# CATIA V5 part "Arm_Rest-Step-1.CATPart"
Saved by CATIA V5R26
Part number: Arm_Rest
Bounding box of the stored display mesh (mm): x 766.704 to 1406.055, y -782.252 to -669.745, z 394.638 to 524.862
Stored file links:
  D:\LinkedIn Learning\NURBS\CATIA\Class Parts\Arm_Rest-Step-1.CATPart
  D:\LinkedIn Learning\NURBS\Arm_Rest.CATPart
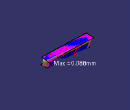
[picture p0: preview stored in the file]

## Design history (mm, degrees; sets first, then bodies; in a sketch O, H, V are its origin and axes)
AxisSystem1: origin (0, 0, 0), X (1, 0, 0), Y (0, 1, 0), Z (0, 0, 1)
StDynAnalysisRootNodeFeature1 "CATStDynAnalysisRootNodeName"
Set1 "REF DATA"
  CLDGeom1 "TOP"
  CLDGeom2 "FRONT"
  CLDGeom3 "AFT_BLEND"
  CLDGeom4 "END_AFT"
  CLDGeom5 "FORWARD_BLEND"
  CLDGeom6 "BOTTOM"
  CLDGeom7 "END_FORWARD"
  CLDGeom8 "UPPER_BLENDS"
  CLDGeom9 "LOWER_BLENDS"
  DatumSurface1 "DOOR_TRIM_SURFACE"
Set2 "FORM"
  Set3 "SLABS"
    DatumSurface2
    DatumSurface3
Body1 (main body)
